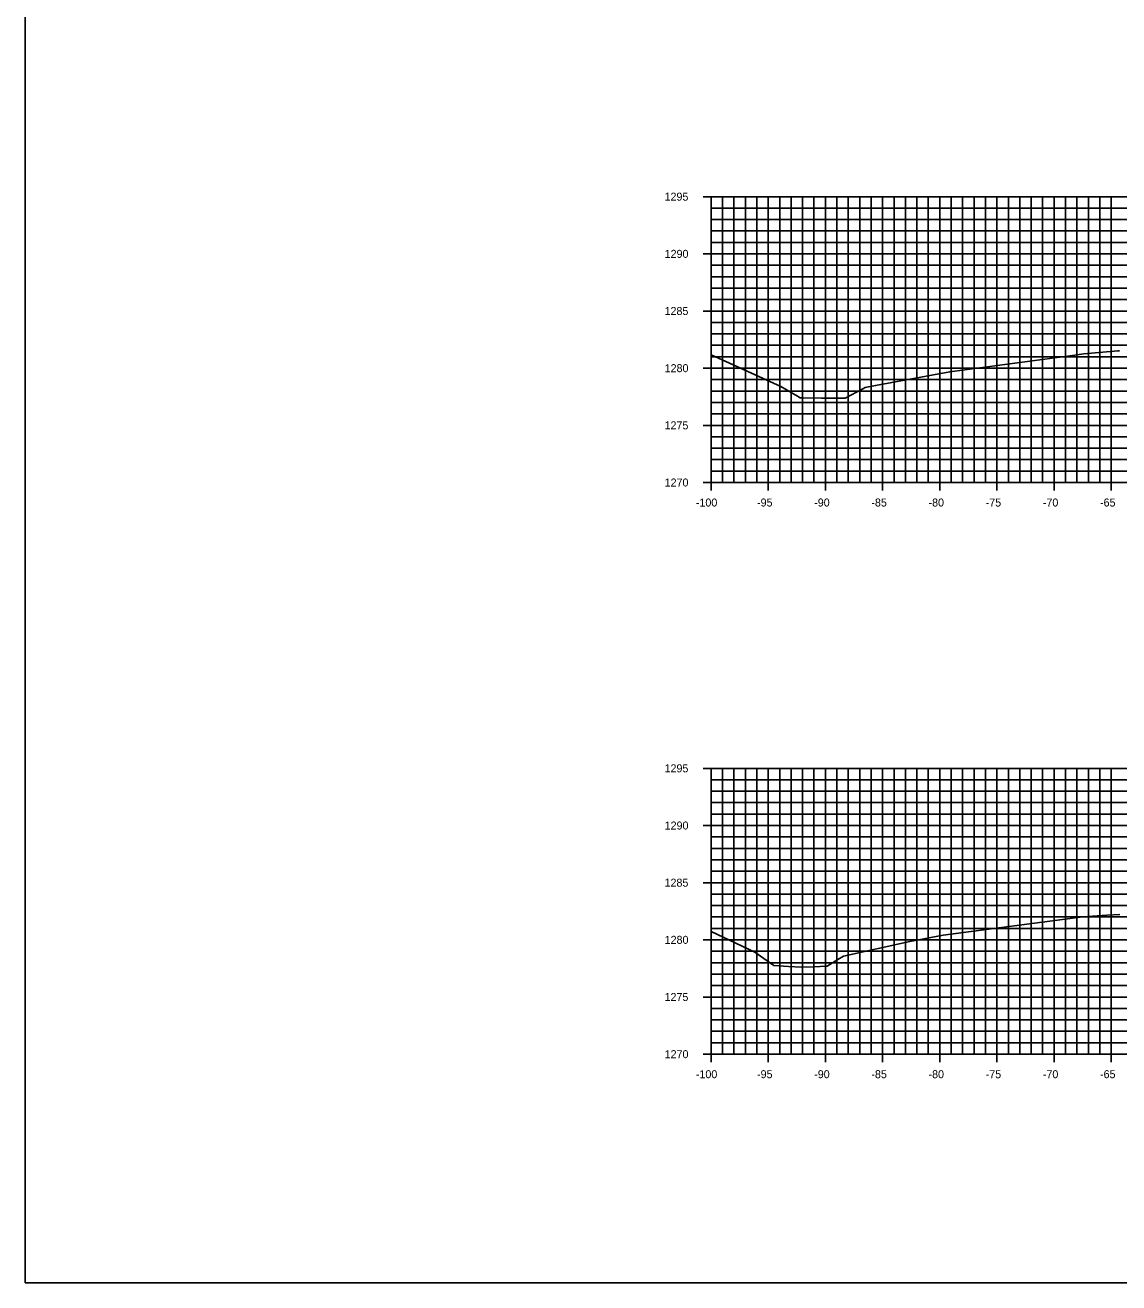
# Model space of a CAD drawing. Extents: x 674939 to 678919, y 750652 to 765176.
# Drawn here: x 678578.5 to 678674.2, y 755752.6 to 755862.6 of the extents above; entities that cross this region are included whole.
import ezdxf

# ---------------------------------------------------------------- set-up
doc = ezdxf.new("R2010")
doc.units = 0
for name, color, linetype in [('Level 10', 7, 'Continuous'), ('Level 20', 7, 'Continuous'), ('Level 4', 7, 'Continuous'), ('Level 8', 7, 'Continuous'), ('Level 9', 7, 'Continuous')]:
    doc.layers.add(name, color=color, linetype=linetype)

msp = doc.modelspace()

# ---------------------------------------------------------------- linework, layer by layer
at = {"layer": 'Level 10'}
for points in [[(678638.53, 755833.72), (678644.64, 755830.96), (678646.1, 755830.09), (678646.32, 755829.96), (678646.57, 755829.95), (678648.19, 755829.93), (678648.48, 755829.93), (678650.27, 755829.93), (678651.79, 755830.75), (678652.01, 755830.87), (678652.92, 755831.03), (678659.41, 755832.24), (678670.36, 755833.7), (678670.93, 755833.78), (678671.12, 755833.79), (678674.1, 755834.07), (678674.24, 755834.08)], [(678638.53, 755783.27), (678642.36, 755781.48), (678643.13, 755780.93), (678644.01, 755780.31), (678645.29, 755780.23), (678646.44, 755780.17), (678647.45, 755780.2), (678648.69, 755780.25), (678649.62, 755780.83), (678650.12, 755781.13), (678655.9, 755782.4), (678658.83, 755782.97), (678662.16, 755783.4), (678671.04, 755784.57), (678673.14, 755784.72), (678674.27, 755784.78)]]:
    msp.add_lwpolyline(points, dxfattribs=at)
at = {"layer": 'Level 20'}
for p, q in [((678638.53, 755847.55), (678838.53, 755847.55)), ((678638.53, 755822.55), (678638.53, 755847.55)), ((678639.53, 755822.55), (678639.53, 755847.55)), ((678640.53, 755822.55), (678640.53, 755847.55)), ((678641.53, 755822.55), (678641.53, 755847.55)), ((678642.53, 755822.55), (678642.53, 755847.55)), ((678643.53, 755822.55), (678643.53, 755847.55)), ((678644.53, 755822.55), (678644.53, 755847.55)), ((678645.53, 755822.55), (678645.53, 755847.55)), ((678646.53, 755822.55), (678646.53, 755847.55)), ((678647.53, 755822.55), (678647.53, 755847.55)), ((678648.53, 755822.55), (678648.53, 755847.55)), ((678649.53, 755822.55), (678649.53, 755847.55)), ((678650.53, 755822.55), (678650.53, 755847.55)), ((678651.53, 755822.55), (678651.53, 755847.55)), ((678652.53, 755822.55), (678652.53, 755847.55)), ((678653.53, 755822.55), (678653.53, 755847.55)), ((678654.53, 755822.55), (678654.53, 755847.55)), ((678655.53, 755822.55), (678655.53, 755847.55)), ((678656.53, 755822.55), (678656.53, 755847.55)), ((678657.53, 755822.55), (678657.53, 755847.55)), ((678658.53, 755822.55), (678658.53, 755847.55)), ((678659.53, 755822.55), (678659.53, 755847.55)), ((678660.53, 755822.55), (678660.53, 755847.55)), ((678661.53, 755822.55), (678661.53, 755847.55)), ((678662.53, 755822.55), (678662.53, 755847.55)), ((678663.53, 755822.55), (678663.53, 755847.55)), ((678664.53, 755822.55), (678664.53, 755847.55)), ((678665.53, 755822.55), (678665.53, 755847.55)), ((678666.53, 755822.55), (678666.53, 755847.55)), ((678667.53, 755822.55), (678667.53, 755847.55)), ((678668.53, 755822.55), (678668.53, 755847.55)), ((678669.53, 755822.55), (678669.53, 755847.55)), ((678670.53, 755822.55), (678670.53, 755847.55)), ((678671.53, 755822.55), (678671.53, 755847.55)), ((678672.53, 755822.55), (678672.53, 755847.55)), ((678673.53, 755822.55), (678673.53, 755847.55)), ((678638.53, 755846.55), (678838.53, 755846.55)), ((678638.53, 755845.55), (678838.53, 755845.55)), ((678638.53, 755844.55), (678838.53, 755844.55)), ((678638.53, 755843.55), (678838.53, 755843.55)), ((678638.53, 755842.55), (678838.53, 755842.55)), ((678638.53, 755841.55), (678838.53, 755841.55)), ((678638.53, 755840.55), (678838.53, 755840.55)), ((678638.53, 755839.55), (678838.53, 755839.55)), ((678638.53, 755838.55), (678838.53, 755838.55)), ((678638.53, 755837.55), (678838.53, 755837.55)), ((678638.53, 755836.55), (678838.53, 755836.55)), ((678638.53, 755835.55), (678838.53, 755835.55)), ((678638.53, 755834.55), (678838.53, 755834.55)), ((678638.53, 755833.55), (678838.53, 755833.55)), ((678638.53, 755832.55), (678838.53, 755832.55)), ((678638.53, 755831.55), (678838.53, 755831.55)), ((678638.53, 755830.55), (678838.53, 755830.55)), ((678638.53, 755829.55), (678838.53, 755829.55)), ((678638.53, 755828.55), (678838.53, 755828.55)), ((678638.53, 755827.55), (678838.53, 755827.55)), ((678638.53, 755826.55), (678838.53, 755826.55)), ((678638.53, 755825.55), (678838.53, 755825.55)), ((678638.53, 755824.55), (678838.53, 755824.55)), ((678638.53, 755823.55), (678838.53, 755823.55)), ((678638.53, 755822.55), (678838.53, 755822.55)), ((678638.53, 755797.55), (678838.53, 755797.55)), ((678638.53, 755772.55), (678638.53, 755797.55)), ((678639.53, 755772.55), (678639.53, 755797.55)), ((678640.53, 755772.55), (678640.53, 755797.55)), ((678641.53, 755772.55), (678641.53, 755797.55)), ((678642.53, 755772.55), (678642.53, 755797.55)), ((678643.53, 755772.55), (678643.53, 755797.55)), ((678644.53, 755772.55), (678644.53, 755797.55)), ((678645.53, 755772.55), (678645.53, 755797.55)), ((678646.53, 755772.55), (678646.53, 755797.55)), ((678647.53, 755772.55), (678647.53, 755797.55)), ((678648.53, 755772.55), (678648.53, 755797.55)), ((678649.53, 755772.55), (678649.53, 755797.55)), ((678650.53, 755772.55), (678650.53, 755797.55)), ((678651.53, 755772.55), (678651.53, 755797.55)), ((678652.53, 755772.55), (678652.53, 755797.55)), ((678653.53, 755772.55), (678653.53, 755797.55)), ((678654.53, 755772.55), (678654.53, 755797.55)), ((678655.53, 755772.55), (678655.53, 755797.55)), ((678656.53, 755772.55), (678656.53, 755797.55)), ((678657.53, 755772.55), (678657.53, 755797.55)), ((678658.53, 755772.55), (678658.53, 755797.55)), ((678659.53, 755772.55), (678659.53, 755797.55)), ((678660.53, 755772.55), (678660.53, 755797.55)), ((678661.53, 755772.55), (678661.53, 755797.55)), ((678662.53, 755772.55), (678662.53, 755797.55)), ((678663.53, 755772.55), (678663.53, 755797.55)), ((678664.53, 755772.55), (678664.53, 755797.55)), ((678665.53, 755772.55), (678665.53, 755797.55)), ((678666.53, 755772.55), (678666.53, 755797.55)), ((678667.53, 755772.55), (678667.53, 755797.55)), ((678668.53, 755772.55), (678668.53, 755797.55)), ((678669.53, 755772.55), (678669.53, 755797.55)), ((678670.53, 755772.55), (678670.53, 755797.55)), ((678671.53, 755772.55), (678671.53, 755797.55)), ((678672.53, 755772.55), (678672.53, 755797.55)), ((678673.53, 755772.55), (678673.53, 755797.55)), ((678638.53, 755796.55), (678838.53, 755796.55)), ((678638.53, 755795.55), (678838.53, 755795.55)), ((678638.53, 755794.55), (678838.53, 755794.55)), ((678638.53, 755793.55), (678838.53, 755793.55)), ((678638.53, 755792.55), (678838.53, 755792.55)), ((678638.53, 755791.55), (678838.53, 755791.55)), ((678638.53, 755790.55), (678838.53, 755790.55)), ((678638.53, 755789.55), (678838.53, 755789.55)), ((678638.53, 755788.55), (678838.53, 755788.55)), ((678638.53, 755787.55), (678838.53, 755787.55)), ((678638.53, 755786.55), (678838.53, 755786.55)), ((678638.53, 755785.55), (678838.53, 755785.55)), ((678638.53, 755784.55), (678838.53, 755784.55)), ((678638.53, 755783.55), (678838.53, 755783.55)), ((678638.53, 755782.55), (678838.53, 755782.55)), ((678638.53, 755781.55), (678838.53, 755781.55)), ((678638.53, 755780.55), (678838.53, 755780.55)), ((678638.53, 755779.55), (678838.53, 755779.55)), ((678638.53, 755778.55), (678838.53, 755778.55)), ((678638.53, 755777.55), (678838.53, 755777.55)), ((678638.53, 755776.55), (678838.53, 755776.55)), ((678638.53, 755775.55), (678838.53, 755775.55)), ((678638.53, 755774.55), (678838.53, 755774.55)), ((678638.53, 755773.55), (678838.53, 755773.55)), ((678638.53, 755772.55), (678838.53, 755772.55))]:
    msp.add_line(p, q, dxfattribs=at)
at = {"layer": 'Level 4'}
msp.add_lwpolyline([(678578.53, 755752.55), (678918.53, 755752.55), (678918.53, 755972.55), (678578.53, 755972.55)], close=True, dxfattribs=at)
at = {"layer": 'Level 8'}
for p, q in [((678637.83, 755847.55), (678639.23, 755847.55)), ((678638.53, 755822.55), (678638.53, 755847.55)), ((678638.53, 755846.55), (678638.88, 755846.55)), ((678638.53, 755845.55), (678638.88, 755845.55)), ((678638.53, 755844.55), (678638.88, 755844.55)), ((678638.53, 755843.55), (678638.88, 755843.55)), ((678637.83, 755842.55), (678639.23, 755842.55)), ((678638.53, 755841.55), (678638.88, 755841.55)), ((678638.53, 755840.55), (678638.88, 755840.55)), ((678638.53, 755839.55), (678638.88, 755839.55)), ((678637.83, 755837.55), (678639.23, 755837.55)), ((678638.53, 755838.55), (678638.88, 755838.55)), ((678638.53, 755836.55), (678638.88, 755836.55)), ((678638.53, 755835.55), (678638.88, 755835.55)), ((678638.53, 755834.55), (678638.88, 755834.55)), ((678638.53, 755833.55), (678638.88, 755833.55)), ((678637.83, 755832.55), (678639.23, 755832.55)), ((678638.53, 755831.55), (678638.88, 755831.55)), ((678638.53, 755830.55), (678638.88, 755830.55)), ((678638.53, 755829.55), (678638.88, 755829.55)), ((678638.53, 755828.55), (678638.88, 755828.55)), ((678637.83, 755827.55), (678639.23, 755827.55)), ((678638.53, 755826.55), (678638.88, 755826.55)), ((678638.53, 755825.55), (678638.88, 755825.55)), ((678638.53, 755824.55), (678638.88, 755824.55)), ((678638.53, 755823.55), (678638.88, 755823.55)), ((678638.53, 755821.85), (678638.53, 755823.25)), ((678643.53, 755821.85), (678643.53, 755823.25)), ((678648.53, 755821.85), (678648.53, 755823.25)), ((678653.53, 755821.85), (678653.53, 755823.25)), ((678658.53, 755821.85), (678658.53, 755823.25)), ((678663.53, 755821.85), (678663.53, 755823.25)), ((678668.53, 755821.85), (678668.53, 755823.25)), ((678673.53, 755821.85), (678673.53, 755823.25)), ((678637.83, 755822.55), (678639.23, 755822.55)), ((678638.53, 755822.55), (678838.53, 755822.55)), ((678637.83, 755797.55), (678639.23, 755797.55)), ((678638.53, 755772.55), (678638.53, 755797.55)), ((678638.53, 755796.55), (678638.88, 755796.55)), ((678638.53, 755795.55), (678638.88, 755795.55)), ((678638.53, 755794.55), (678638.88, 755794.55)), ((678638.53, 755793.55), (678638.88, 755793.55)), ((678637.83, 755792.55), (678639.23, 755792.55)), ((678638.53, 755791.55), (678638.88, 755791.55)), ((678638.53, 755790.55), (678638.88, 755790.55)), ((678638.53, 755789.55), (678638.88, 755789.55)), ((678638.53, 755788.55), (678638.88, 755788.55)), ((678637.83, 755787.55), (678639.23, 755787.55)), ((678638.53, 755786.55), (678638.88, 755786.55)), ((678638.53, 755785.55), (678638.88, 755785.55)), ((678638.53, 755784.55), (678638.88, 755784.55)), ((678637.83, 755782.55), (678639.23, 755782.55)), ((678638.53, 755783.55), (678638.88, 755783.55)), ((678638.53, 755781.55), (678638.88, 755781.55)), ((678638.53, 755780.55), (678638.88, 755780.55)), ((678638.53, 755779.55), (678638.88, 755779.55)), ((678638.53, 755778.55), (678638.88, 755778.55)), ((678637.83, 755777.55), (678639.23, 755777.55)), ((678638.53, 755776.55), (678638.88, 755776.55)), ((678638.53, 755775.55), (678638.88, 755775.55)), ((678638.53, 755774.55), (678638.88, 755774.55)), ((678638.53, 755773.55), (678638.88, 755773.55)), ((678638.53, 755771.85), (678638.53, 755773.25)), ((678643.53, 755771.85), (678643.53, 755773.25)), ((678648.53, 755771.85), (678648.53, 755773.25)), ((678653.53, 755771.85), (678653.53, 755773.25)), ((678658.53, 755771.85), (678658.53, 755773.25)), ((678663.53, 755771.85), (678663.53, 755773.25)), ((678668.53, 755771.85), (678668.53, 755773.25)), ((678673.53, 755771.85), (678673.53, 755773.25)), ((678637.83, 755772.55), (678639.23, 755772.55)), ((678638.53, 755772.55), (678838.53, 755772.55))]:
    msp.add_line(p, q, dxfattribs=at)

# ---------------------------------------------------------------- texts
at = {"layer": 'Level 9'}
for s, p in [('1295', (678634.46, 755847.2)), ('1290', (678634.47, 755842.2)), ('1285', (678634.46, 755837.2)), ('1280', (678634.47, 755832.2)), ('1275', (678634.46, 755827.2)), ('1270', (678634.47, 755822.2)), ('-100', (678637.2, 755820.45)), ('-95', (678642.55, 755820.45)), ('-90', (678647.55, 755820.45)), ('-85', (678652.55, 755820.45)), ('-80', (678657.55, 755820.45)), ('-75', (678662.55, 755820.45)), ('-70', (678667.55, 755820.45)), ('-65', (678672.55, 755820.45)), ('1295', (678634.46, 755797.2)), ('1290', (678634.47, 755792.2)), ('1285', (678634.46, 755787.2)), ('1280', (678634.47, 755782.2)), ('1275', (678634.46, 755777.2)), ('1270', (678634.47, 755772.2)), ('-100', (678637.2, 755770.45)), ('-95', (678642.55, 755770.45)), ('-90', (678647.55, 755770.45)), ('-85', (678652.55, 755770.45)), ('-80', (678657.55, 755770.45)), ('-75', (678662.55, 755770.45)), ('-70', (678667.55, 755770.45)), ('-65', (678672.55, 755770.45))]:
    msp.add_text(s, height=0.7, dxfattribs=at).set_placement(p)

doc.saveas('drawing.dxf')
